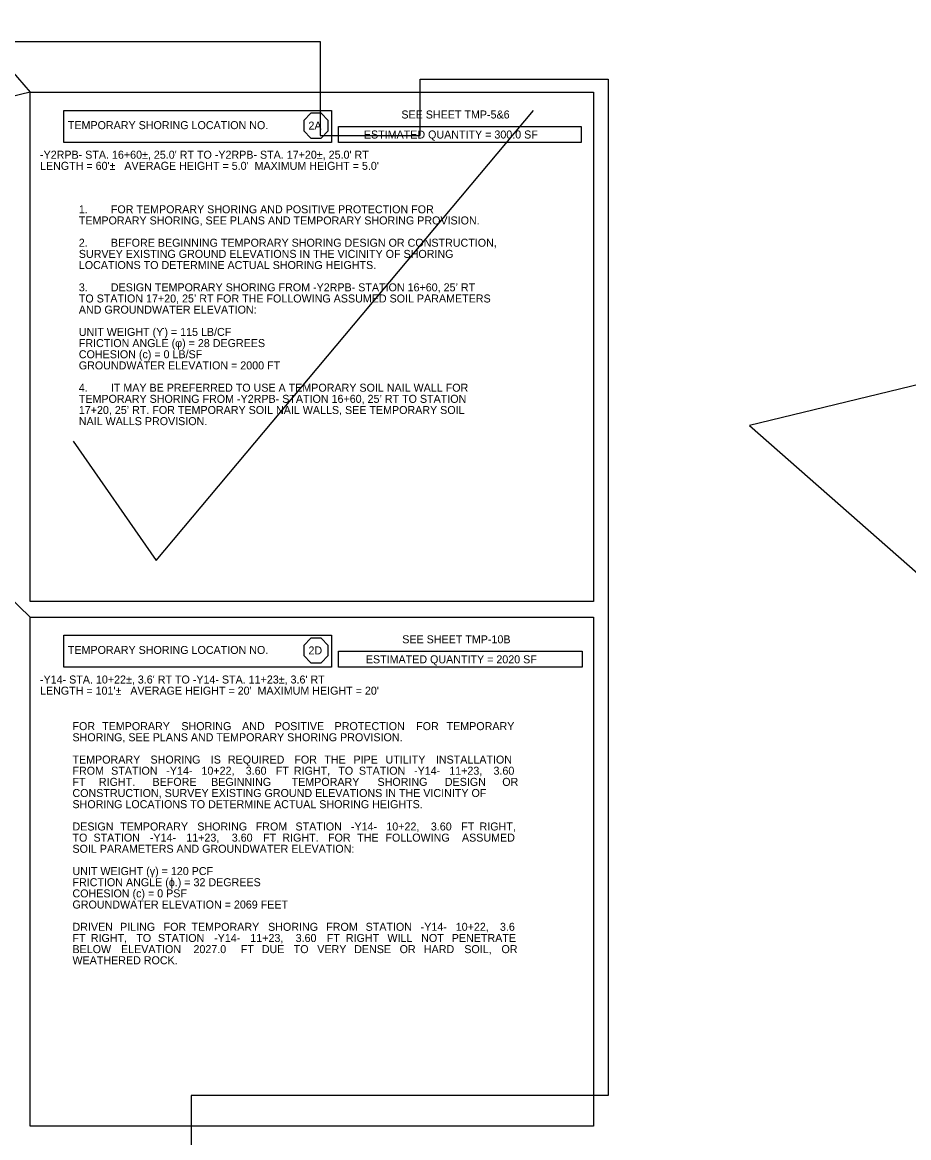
# Model space of a CAD drawing. Extents: x 2487012 to 2497594, y 369516 to 371986.
# Drawn here: x 2490008 to 2490762, y 370349 to 371299 of the extents above; entities that cross this region are included whole.
import ezdxf

# ---------------------------------------------------------------- set-up
doc = ezdxf.new("R2010")
doc.units = 0
for name, color, linetype in [('Scratch_Level_2', 7, 'Continuous'), ('Scratch_Level_6', 7, 'Continuous'), ('TC LABEL TEMP SHORING', 7, 'Continuous'), ('TC SHEET BORDER LINE THIN', 7, 'Continuous'), ('TC SHEET LAYOUT SHAPE', 7, 'Continuous'), ('TC SHEET TEXT', 7, 'Continuous')]:
    doc.layers.add(name, color=color, linetype=linetype)

msp = doc.modelspace()

# ---------------------------------------------------------------- linework, layer by layer
at = {"layer": 'Scratch_Level_2'}
msp.add_lwpolyline([(2490051.18, 370941.91), (2490121.97, 370840.49), (2490442.97, 371223.61)], dxfattribs=at)
at = {"layer": 'Scratch_Level_6'}
for points in [[(2489016.56, 371282.27), (2489028.88, 371239.13), (2489430.44, 371433.43), (2489521.78, 371239.13), (2489836.55, 371445.42), (2490014.68, 371239.13), (2488843.26, 370955.22), (2489028.88, 370792.26), (2489389.17, 370953.89), (2489521.78, 370792.26), (2489877.82, 370924.58), (2490014.68, 370792.26)], [(2490800.31, 371282.27), (2490812.63, 371239.13), (2491214.19, 371433.43), (2491305.53, 371239.13), (2491620.29, 371445.42), (2491798.43, 371239.13), (2490627, 370955.22), (2490812.63, 370792.26), (2491172.91, 370953.89), (2491305.53, 370792.26), (2491661.57, 370924.58), (2491798.43, 370792.26)]]:
    msp.add_lwpolyline(points, dxfattribs=at)
at = {"layer": 'TC LABEL TEMP SHORING'}
for p, q in [((2490253.64, 371221.17), (2490247.55, 371215.01)), ((2490247.55, 371215.01), (2490247.55, 371206.28)), ((2490262.24, 371221.17), (2490253.64, 371221.17)), ((2490268.33, 371215.01), (2490262.24, 371221.17)), ((2490268.33, 371206.28), (2490268.33, 371215.01)), ((2490247.55, 371206.28), (2490253.64, 371200.12)), ((2490262.24, 371200.12), (2490268.33, 371206.28)), ((2490253.64, 371200.12), (2490262.24, 371200.12)), ((2490253.64, 370774.3), (2490247.55, 370768.13)), ((2490247.55, 370768.13), (2490247.55, 370759.41)), ((2490262.24, 370774.3), (2490253.64, 370774.3)), ((2490268.33, 370768.13), (2490262.24, 370774.3)), ((2490268.33, 370759.41), (2490268.33, 370768.13)), ((2490247.55, 370759.41), (2490253.64, 370753.24)), ((2490262.24, 370753.24), (2490268.33, 370759.41)), ((2490253.64, 370753.24), (2490262.24, 370753.24))]:
    msp.add_line(p, q, dxfattribs=at)
at = {"layer": 'TC SHEET BORDER LINE THIN'}
for points in [[(2490014.68, 371239.13), (2490494.12, 371239.13), (2490494.12, 370805.5), (2490014.68, 370805.5)], [(2490043.16, 371223.55), (2490271.22, 371223.55), (2490271.22, 371196.29), (2490043.16, 371196.29)], [(2490276.98, 371209.92), (2490483.78, 371209.92), (2490483.78, 371196.29), (2490276.98, 371196.29)], [(2490014.68, 370792.26), (2490494.12, 370792.26), (2490494.12, 370358.63), (2490014.68, 370358.63)], [(2490043.16, 370776.68), (2490271.22, 370776.68), (2490271.22, 370749.42), (2490043.16, 370749.42)], [(2490276.98, 370763.05), (2490484.45, 370763.05), (2490484.45, 370749.42), (2490276.98, 370749.42)]]:
    msp.add_lwpolyline(points, close=True, dxfattribs=at)
at = {"layer": 'TC SHEET LAYOUT SHAPE'}
msp.add_lwpolyline([(2489016.56, 370690.84), (2489016.56, 371000.16), (2489016.56, 371272.27), (2489026.56, 371282.27), (2489469.58, 371282.27), (2489940.56, 371282.27), (2490261.56, 371282.27), (2490261.56, 371202.27), (2490346.56, 371202.27), (2490346.56, 371250.27), (2490506.56, 371250.27), (2490506.56, 370915.3), (2490506.56, 370636.1), (2490506.56, 370384.77), (2490151.56, 370384.77), (2490151.56, 370242.27), (2489778.38, 370242.27), (2489608.92, 370242.27), (2489256.14, 370242.27), (2489016.56, 370242.27)], close=True, dxfattribs=at)

# ---------------------------------------------------------------- texts
at = {"layer": 'TC LABEL TEMP SHORING'}
for s, p in [('2A', (2490251.53, 371207.28)), ('2D', (2490251.53, 370760.41))]:
    msp.add_text(s, height=6.814, dxfattribs=at).set_placement(p)
at = {"layer": 'TC SHEET BORDER LINE THIN'}
for s, height, p in [('1.', 6.814, (2490056.06, 371136.03)), ('FOR TEMPORARY SHORING AND POSITIVE PROTECTION FOR ', 6.8137, (2490083.32, 371136.03)), ('TEMPORARY SHORING, SEE PLANS AND TEMPORARY SHORING PROVISION.', 6.8137, (2490056.06, 371126.54)), ('2.', 6.814, (2490056.06, 371107.55)), ('BEFORE BEGINNING TEMPORARY SHORING DESIGN OR CONSTRUCTION, ', 6.8137, (2490083.32, 371107.55)), ('SURVEY EXISTING GROUND ELEVATIONS IN THE VICINITY OF SHORING ', 6.8137, (2490056.06, 371098.05)), ('LOCATIONS TO DETERMINE ACTUAL SHORING HEIGHTS.', 6.8137, (2490056.06, 371088.56)), ('3.', 6.814, (2490056.06, 371069.57)), ('DESIGN TEMPORARY SHORING FROM -Y2RPB- STATION 16+60, 25’ RT ', 6.8137, (2490083.32, 371069.57)), ('TO STATION 17+20, 25’ RT FOR THE FOLLOWING ASSUMED SOIL PARAMETERS ', 6.8137, (2490056.06, 371060.08)), ('AND GROUNDWATER ELEVATION:', 6.8137, (2490056.06, 371050.58)), ('UNIT WEIGHT (ϒ) = 115 LB/CF', 6.8137, (2490056.06, 371031.59)), ('FRICTION ANGLE (φ) = 28 DEGREES', 6.8137, (2490056.06, 371022.1)), ('COHESION (c) = 0 LB/SF', 6.8137, (2490056.06, 371012.6)), ('GROUNDWATER ELEVATION = 2000 FT', 6.8137, (2490056.06, 371003.11)), ('4.', 6.814, (2490056.06, 370984.12)), ('IT MAY BE PREFERRED TO USE A TEMPORARY SOIL NAIL WALL FOR ', 6.8137, (2490083.32, 370984.12)), ('TEMPORARY SHORING FROM -Y2RPB- STATION 16+60, 25’ RT TO STATION ', 6.8137, (2490056.06, 370974.63)), ('17+20, 25’ RT. FOR TEMPORARY SOIL NAIL WALLS, SEE TEMPORARY SOIL ', 6.8137, (2490056.06, 370965.13)), ('NAIL WALLS PROVISION.', 6.8137, (2490056.06, 370955.64)), ('FOR ', 6.814, (2490050.64, 370695.95)), ('TEMPORARY ', 6.814, (2490075.88, 370695.95)), ('SHORING ', 6.814, (2490143.36, 370695.95)), ('AND ', 6.814, (2490195.05, 370695.95)), ('POSITIVE ', 6.814, (2490222.83, 370695.95)), ('PROTECTION ', 6.8137, (2490273.8, 370695.95)), ('FOR ', 6.814, (2490343.2, 370695.95)), ('TEMPORARY ', 6.814, (2490369.11, 370695.95)), ('SHORING, SEE PLANS AND TEMPORARY SHORING PROVISION.', 6.8137, (2490050.64, 370686.46)), ('TEMPORARY ', 6.814, (2490050.64, 370667.47)), ('SHORING ', 6.814, (2490117.06, 370667.47)), ('IS ', 6.814, (2490168.35, 370667.47)), ('REQUIRED ', 6.814, (2490182.95, 370667.47)), ('FOR ', 6.814, (2490239.51, 370667.47)), ('THE ', 6.814, (2490265.02, 370667.47)), ('PIPE ', 6.814, (2490289.82, 370667.47)), ('UTILITY ', 6.814, (2490317.17, 370667.47)), ('INSTALLATION ', 6.8137, (2490360.01, 370667.47)), ('FROM ', 6.814, (2490050.64, 370657.98)), ('STATION ', 6.814, (2490083.59, 370657.98)), ('-Y14- ', 6.814, (2490130.52, 370657.98)), ('10+22, ', 6.814, (2490160.45, 370657.98)), ('3.60 ', 6.814, (2490198.14, 370657.98)), ('FT ', 6.814, (2490223.73, 370657.98)), ('RIGHT, ', 6.814, (2490239.12, 370657.98)), ('TO ', 6.814, (2490276.94, 370657.98)), ('STATION ', 6.814, (2490294.5, 370657.98)), ('-Y14- ', 6.814, (2490341.44, 370657.98)), ('11+23, ', 6.814, (2490371.37, 370657.98)), ('3.60 ', 6.814, (2490409.06, 370657.98)), ('FT ', 6.814, (2490050.64, 370648.48)), ('RIGHT. ', 6.814, (2490073.14, 370648.48)), ('BEFORE ', 6.814, (2490118.77, 370648.48)), ('BEGINNING ', 6.814, (2490168.66, 370648.48)), ('TEMPORARY ', 6.814, (2490237.2, 370648.48)), ('SHORING ', 6.814, (2490310.32, 370648.48)), ('DESIGN ', 6.814, (2490367.65, 370648.48)), ('OR ', 6.814, (2490416.53, 370648.48)), ('CONSTRUCTION, SURVEY EXISTING GROUND ELEVATIONS IN THE VICINITY OF ', 6.8137, (2490050.64, 370638.99)), ('SHORING LOCATIONS TO DETERMINE ACTUAL SHORING HEIGHTS.', 6.8137, (2490050.64, 370629.49)), ('DESIGN ', 6.814, (2490050.64, 370610.5)), ('TEMPORARY ', 6.814, (2490091.3, 370610.5)), ('SHORING ', 6.814, (2490156.87, 370610.5)), ('FROM ', 6.814, (2490206.65, 370610.5)), ('STATION ', 6.814, (2490240.5, 370610.5)), ('-Y14- ', 6.814, (2490287.67, 370610.5)), ('10+22, ', 6.814, (2490317.83, 370610.5)), ('3.60 ', 6.814, (2490355.75, 370610.5)), ('FT ', 6.814, (2490381.58, 370610.5)), ('RIGHT, ', 6.814, (2490397.19, 370610.5)), ('TO ', 6.814, (2490050.64, 370601.01)), ('STATION ', 6.814, (2490068.57, 370601.01)), ('-Y14- ', 6.814, (2490116.55, 370601.01)), ('11+23, ', 6.814, (2490147.51, 370601.01)), ('3.60 ', 6.814, (2490186.25, 370601.01)), ('FT ', 6.814, (2490212.88, 370601.01)), ('RIGHT. ', 6.814, (2490229.31, 370601.01)), ('FOR ', 6.814, (2490268.2, 370601.01)), ('THE ', 6.814, (2490293, 370601.01)), ('FOLLOWING ', 6.814, (2490317.09, 370601.01)), ('ASSUMED ', 6.814, (2490382.19, 370601.01)), ('SOIL PARAMETERS AND GROUNDWATER ELEVATION:', 6.8137, (2490050.64, 370591.52)), ('UNIT WEIGHT (γ) = 120 PCF', 6.8137, (2490050.64, 370572.53)), ('FRICTION ANGLE (ϕ.) = 32 DEGREES', 6.8137, (2490050.64, 370563.03)), ('COHESION (c) = 0 PSF', 6.8137, (2490050.64, 370553.54)), ('GROUNDWATER ELEVATION = 2069 FEET', 6.8137, (2490050.64, 370544.04)), ('DRIVEN ', 6.814, (2490050.64, 370525.06)), ('PILING ', 6.814, (2490091.21, 370525.06)), ('FOR ', 6.814, (2490128.22, 370525.06)), ('TEMPORARY ', 6.814, (2490151.91, 370525.06)), ('SHORING ', 6.814, (2490217.18, 370525.06)), ('FROM ', 6.814, (2490266.66, 370525.06)), ('STATION ', 6.814, (2490300.2, 370525.06)), ('-Y14- ', 6.814, (2490347.07, 370525.06)), ('10+22, ', 6.814, (2490376.93, 370525.06)), ('3.6 ', 6.814, (2490414.55, 370525.06)), ('FT ', 6.814, (2490050.64, 370515.56)), ('RIGHT, ', 6.814, (2490066.25, 370515.56)), ('TO ', 6.814, (2490104.96, 370515.56)), ('STATION ', 6.814, (2490123.41, 370515.56)), ('-Y14- ', 6.814, (2490171.24, 370515.56)), ('11+23, ', 6.814, (2490202.05, 370515.56)), ('3.60 ', 6.814, (2490240.63, 370515.56)), ('FT ', 6.814, (2490267.12, 370515.56)), ('RIGHT ', 6.814, (2490283.39, 370515.56)), ('WILL ', 6.814, (2490318.75, 370515.56)), ('NOT ', 6.814, (2490347.49, 370515.56)), ('PENETRATE ', 6.814, (2490373.54, 370515.56)), ('BELOW ', 6.814, (2490050.64, 370506.07)), ('ELEVATION ', 6.814, (2490091.95, 370506.07)), ('2027.0 ', 6.814, (2490153.65, 370506.07)), ('FT ', 6.814, (2490193.95, 370506.07)), ('DUE ', 6.814, (2490211.84, 370506.07)), ('TO ', 6.814, (2490238.96, 370506.07)), ('VERY ', 6.814, (2490259.01, 370506.07)), ('DENSE ', 6.814, (2490290.47, 370506.07)), ('OR ', 6.814, (2490329.14, 370506.07)), ('HARD ', 6.814, (2490349.79, 370506.07)), ('SOIL, ', 6.814, (2490384.18, 370506.07)), ('OR ', 6.814, (2490415.85, 370506.07)), ('WEATHERED ROCK.', 6.8137, (2490050.64, 370496.57))]:
    msp.add_text(s, height=height, dxfattribs=at).set_placement(p)
at = {"layer": 'TC SHEET TEXT'}
for s, p in [('SEE SHEET TMP-5&6', (2490330.63, 371216.75)), ('TEMPORARY SHORING LOCATION NO.', (2490046.73, 371207.68)), ('ESTIMATED QUANTITY = 300.0 SF', (2490298.7, 371199.7)), ("-Y2RPB- STA. 16+60±, 25.0' RT TO -Y2RPB- STA. 17+20±, 25.0' RT", (2490023.01, 371182.51)), ("LENGTH = 60'±   AVERAGE HEIGHT = 5.0'  MAXIMUM HEIGHT = 5.0'", (2490023.01, 371173.02)), ('SEE SHEET TMP-10B', (2490331.39, 370769.88)), ('TEMPORARY SHORING LOCATION NO.', (2490046.73, 370760.81)), ('ESTIMATED QUANTITY = 2020 SF', (2490300.38, 370752.83)), ("-Y14- STA. 10+22±, 3.6' RT TO -Y14- STA. 11+23±, 3.6' RT", (2490023.01, 370735.64)), ("LENGTH = 101'±   AVERAGE HEIGHT = 20'  MAXIMUM HEIGHT = 20'", (2490023.01, 370726.15))]:
    msp.add_text(s, height=6.8137, dxfattribs=at).set_placement(p)

doc.saveas('drawing.dxf')
